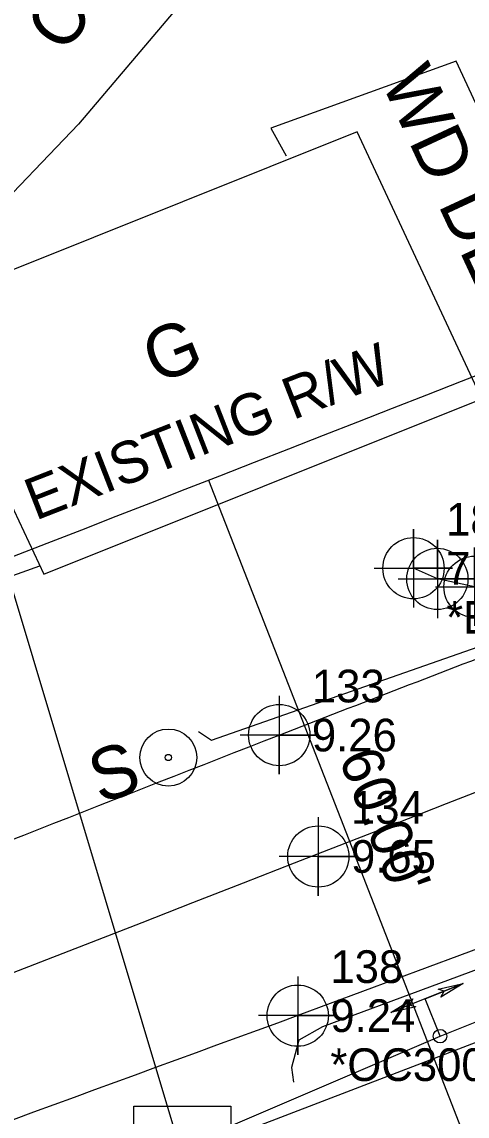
# Model space of a CAD drawing. Extents: x 2597630 to 2605918, y 617194 to 635093.
# Drawn here: x 2604013.5 to 2604047.6, y 618660.8 to 618744.5 of the extents above; entities that cross this region are included whole.
import ezdxf

# ---------------------------------------------------------------- set-up
doc = ezdxf.new("R2010")
doc.units = 0
for name, color, linetype in [('COGO Default Chain', 7, 'Continuous'), ('COGO Default Curve', 7, 'Continuous'), ('Default', 7, 'Continuous'), ('Exist Building', 7, 'Continuous'), ('Exist Building Text', 7, 'Continuous'), ('Exist DTM Crownline Cogo Elevation', 7, 'Continuous'), ('Exist DTM Crownline Cogo Number', 7, 'Continuous'), ('Exist DTM Crownline Cogo Point CELL', 7, 'Continuous'), ('Exist Guardrail', 7, 'Continuous'), ('Exist Horizontal Alignment', 7, 'Continuous'), ('Exist Horizontal Baseline Alignment Station Label', 7, 'Continuous'), ('Exist Other Culture Area Outline', 7, 'Continuous'), ('Exist Other Culture Area Outline Text', 7, 'Continuous'), ('Exist Other Culture Located Object CELL', 7, 'Continuous'), ('Exist Other Culture Located Object Text', 7, 'Continuous'), ('Exist Right of Way Line', 7, 'Continuous'), ('Exist Right of Way Line Text', 7, 'Continuous'), ('Exist Right of Way Width CELL', 7, 'Continuous'), ('Exist Roads EOP', 7, 'Continuous'), ('Exist Roads EOP Cogo Comment', 7, 'Continuous'), ('Exist Roads EOP Cogo Elevation', 7, 'Continuous'), ('Exist Roads EOP Cogo Number', 7, 'Continuous'), ('Exist Roads EOP Cogo Point CELL', 7, 'Continuous'), ('Exist Roads EOP Other', 7, 'Continuous'), ('Exist Roads EOP Other Text', 7, 'Continuous'), ('Exist Roads Soil', 7, 'Continuous'), ('Exist Structure Major Bridge WW', 7, 'Continuous'), ('Exist Structure Major Bridge WW Cogo Comment', 7, 'Continuous'), ('Exist Structure Major Bridge WW Cogo Elevation', 7, 'Continuous'), ('Exist Structure Major Bridge WW Cogo Number', 7, 'Continuous'), ('Exist Structure Major Bridge WW Cogo Point CELL', 7, 'Continuous'), ('Exist Utilities Water Change of Service SUE CELL', 7, 'Continuous'), ('Exist Utilities Water UG Line SUE LOS B', 7, 'Continuous'), ('Exist Utilities Water UG Line SUE LOS C', 7, 'Continuous')]:
    doc.layers.add(name, color=color, linetype=linetype)

# ---------------------------------------------------------------- blocks, each defined once
blk = doc.blocks.new('EXIST OTHER CULTURE LOCATED OBJECT')
at = {"layer": 'Exist Other Culture Located Object CELL'}
for radius in [0.0436, 0.0048]:
    blk.add_circle((0, 0), radius, dxfattribs=at)
blk = doc.blocks.new('CTL SUPPLEMENTAL HORIZONTAL AND VERTICAL')
at = {"layer": 'Default'}
blk.add_line((0, 0), (0, 0), dxfattribs=at)
blk.add_lwpolyline([(-0.1043, 0.0004), (0.0005, 0.1052), (0.1055, 0.0002), (0.0007, -0.1047)], close=True, dxfattribs=at)
blk = doc.blocks.new('EXIST DTM CROWNLINE COGO POINT')
at = {"layer": 'Exist DTM Crownline Cogo Point CELL'}
blk.add_lwpolyline([(0, 0.06), (0, -0.06), (0, 0), (0.06, 0), (-0.06, 0)], dxfattribs=at)
blk.add_circle((0, 0), 0.0469, dxfattribs=at)
blk = doc.blocks.new('EXIST ROADS EOP COGO POINT')
at = {"layer": 'Exist Roads EOP Cogo Point CELL'}
blk.add_lwpolyline([(0, 0.06), (0, -0.06), (0, 0), (0.06, 0), (-0.06, 0)], dxfattribs=at)
blk.add_circle((0, 0), 0.0469, dxfattribs=at)
blk = doc.blocks.new('EXIST STRUCTURE MAJOR BRIDGE WW COGO POINT')
at = {"layer": 'Exist Structure Major Bridge WW Cogo Point CELL'}
blk.add_lwpolyline([(-0.06, 0), (0.06, 0), (0, 0), (0, 0.06), (0, -0.06)], dxfattribs=at)
blk.add_circle((0, 0), 0.0469, dxfattribs=at)

msp = doc.modelspace()

# ---------------------------------------------------------------- linework, layer by layer
at = {"layer": 'COGO Default Chain'}
msp.add_line((2604025.781, 618657.828), (2604635.42, 618891.582), dxfattribs=at)
msp.add_line((2604025.781, 618657.828), (2604635.42, 618891.582), dxfattribs=at)
msp.add_arc((2597632.588, 635089.507), 17613.895, 290.3221155, 292.0583016, dxfattribs=at)
msp.add_arc((2597632.588, 635089.507), 17613.895, 290.3221155, 292.0583016, dxfattribs=at)
msp.add_arc((2597632.588, 635089.507), 17613.895, 290.3221155, 292.0583016, dxfattribs=at)
msp.add_arc((2597632.588, 635089.507), 17613.895, 290.3221155, 292.0583016, dxfattribs=at)
msp.add_arc((2597632.588, 635089.507), 17613.895, 290.3221155, 292.0583016, dxfattribs=at)
msp.add_arc((2597632.588, 635089.507), 17613.895, 290.3221155, 292.0583016, dxfattribs=at)
at = {"layer": 'COGO Default Curve'}
msp.add_arc((2597632.588, 635089.507), 17613.895, 290.3221155, 292.0583016, dxfattribs=at)
msp.add_arc((2597632.588, 635089.507), 17613.895, 290.3221155, 292.0583016, dxfattribs=at)
at = {"layer": 'Exist Building'}
msp.add_lwpolyline([(2604015.177, 618702.256), (2604048.721, 618715.695), (2604039.195, 618736.113), (2604005.593, 618722.673)], close=True, dxfattribs=at)
at = {"layer": 'Exist Guardrail'}
for points in [[(2604027.029, 618690.238), (2604028.032, 618689.57), (2604052.016, 618697.945)], [(2604059.732, 618676.217), (2604036.52, 618667.624), (2604034.721, 618666.608), (2604034.156, 618664.52), (2604034.305, 618663.39)]]:
    msp.add_lwpolyline(points, dxfattribs=at)
at = {"layer": 'Exist Horizontal Alignment'}
msp.add_arc((2597632.588, 635089.507), 17613.895, 290.3221155, 292.0583016, dxfattribs=at)
at = {"layer": 'Exist Horizontal Baseline Alignment Station Label'}
msp.add_line((2604025.781, 618657.828), (2603989.259, 618779.421), dxfattribs=at)
at = {"layer": 'Exist Other Culture Area Outline'}
msp.add_lwpolyline([(2604049.02, 618716.922), (2604056.77, 618719.992), (2604046.769, 618741.515), (2604032.571, 618736.399), (2604033.758, 618734.289)], dxfattribs=at)
at = {"layer": 'Exist Right of Way Line'}
for radius, start, end in [(17584.22, 290.3221155, 291.5057379), (17644.22, 291.0267478, 291.4331797)]:
    msp.add_arc((2597632.588, 635089.507), radius, start, end, dxfattribs=at)
at = {"layer": 'Exist Right of Way Width CELL'}
for p in [(2604027.809, 618709.46), (2604049.63, 618653.569)]:
    msp.add_line(p, (2604038.953, 618680.916), dxfattribs=at)
at = {"layer": 'Exist Roads EOP'}
msp.add_line((2604060.323, 618678.03), (2604034.633, 618668.486), dxfattribs=at)
for points in [[(2603230.17, 618389.98), (2603282.929, 618409.597), (2603332.773, 618427.868), (2603388.167, 618448.413), (2603437.203, 618466.721), (2603490.778, 618486.527), (2603539.039, 618504.558), (2603597.451, 618526.156), (2603651.053, 618545.972), (2603705.208, 618566.084), (2603762.02, 618587.183), (2603820.334, 618609.162), (2603876.341, 618629.99), (2603934.909, 618652.28), (2603996.409, 618675.568), (2604033.216, 618689.957), (2604052.01, 618697.199)], [(2604034.633, 618668.486), (2603984.89, 618650.123), (2603936.767, 618631.654), (2603888.195, 618613.335), (2603837.766, 618594.258), (2603782.918, 618573.705), (2603731.939, 618554.39), (2603671.126, 618532.171), (2603621.822, 618514.106), (2603561.545, 618491.877), (2603506.421, 618471.293), (2603452.163, 618451.33), (2603398.364, 618431.316), (2603341.431, 618410.355), (2603281.65, 618388.199), (2603223.033, 618366.475), (2603185.717, 618352.612)]]:
    msp.add_spline(points, degree=3, dxfattribs=at)
at = {"layer": 'Exist Roads EOP Other'}
msp.add_lwpolyline([(2604039.162, 618760.904), (2604028.995, 618750.493), (2604025.241, 618745.421), (2604017.836, 618736.698), (2604010.541, 618729.111), (2604004.643, 618721.649)], dxfattribs=at)
at = {"layer": 'Exist Roads Soil'}
msp.add_lwpolyline([(2604000.332, 618697.708), (2604014.876, 618702.897)], dxfattribs=at)
at = {"layer": 'Exist Structure Major Bridge WW'}
msp.add_lwpolyline([(2604050.92, 618700.387), (2604048.172, 618701.305), (2604045.325, 618701.901), (2604043.496, 618702.72)], dxfattribs=at)
at = {"layer": 'Exist Utilities Water Change of Service SUE CELL'}
for p, q in [((2604047.292, 618670.947), (2604041.759, 618668.724)), ((2604044.383, 618669.778), (2604047.292, 618670.947)), ((2604045.533, 618666.916), (2604044.383, 618669.778)), ((2604045.533, 618666.916), (2604045.533, 618666.916))]:
    msp.add_line(p, q, dxfattribs=at)
for points in [[(2604047.292, 618670.947), (2604045.591, 618669.893), (2604045.853, 618670.369), (2604045.385, 618670.51)], [(2604041.759, 618668.724), (2604043.46, 618669.778), (2604043.198, 618669.302), (2604043.667, 618669.161)]]:
    msp.add_lwpolyline(points, close=True, dxfattribs=at)
msp.add_circle((2604045.533, 618666.916), 0.517, dxfattribs=at)
at = {"layer": 'Exist Utilities Water UG Line SUE LOS B'}
msp.add_lwpolyline([(2603994.43, 618645.048), (2604045.533, 618666.916)], dxfattribs=at)
at = {"layer": 'Exist Utilities Water UG Line SUE LOS C'}
msp.add_line((2604045.533, 618666.916), (2604610.82, 618894.017), dxfattribs=at)

# ---------------------------------------------------------------- block references
at = {"layer": 'Default', "xscale": 50, "yscale": 49.99999999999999, "rotation": 44.99999999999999}
msp.add_blockref('CTL SUPPLEMENTAL HORIZONTAL AND VERTICAL', (2604025.781, 618657.828), dxfattribs=at)
at = {"layer": 'Exist DTM Crownline Cogo Point CELL', "xscale": 50, "yscale": 50}
msp.add_blockref('EXIST DTM CROWNLINE COGO POINT', (2604036.209, 618680.665), dxfattribs=at)
msp.add_blockref('EXIST DTM CROWNLINE COGO POINT', (2604036.209, 618680.665), dxfattribs=at)
at = {"layer": 'Exist Other Culture Located Object CELL', "xscale": 50, "yscale": 50}
msp.add_blockref('EXIST OTHER CULTURE LOCATED OBJECT', (2604024.726, 618688.238), dxfattribs=at)
at = {"layer": 'Exist Roads EOP Cogo Point CELL', "xscale": 50, "yscale": 50}
for p in [(2604033.216, 618689.957), (2604033.216, 618689.957), (2604034.633, 618668.486), (2604034.633, 618668.486)]:
    msp.add_blockref('EXIST ROADS EOP COGO POINT', p, dxfattribs=at)
at = {"layer": 'Exist Structure Major Bridge WW Cogo Point CELL', "xscale": 50, "yscale": 50}
for p in [(2604043.496, 618702.72), (2604043.496, 618702.72), (2604043.496, 618702.72), (2604045.325, 618701.901), (2604045.325, 618701.901), (2604045.325, 618701.901), (2604048.172, 618701.305), (2604048.172, 618701.305), (2604048.172, 618701.305)]:
    msp.add_blockref('EXIST STRUCTURE MAJOR BRIDGE WW COGO POINT', p, dxfattribs=at)

# ---------------------------------------------------------------- texts
at = {"layer": 'Exist Building Text'}
msp.add_text('G', height=4, rotation=21.7998, dxfattribs=at).set_placement((2604023.804, 618716.768))
at = {"layer": 'Exist DTM Crownline Cogo Elevation'}
msp.add_text('9.65', height=2.5, dxfattribs=at).set_placement((2604038.709, 618679.415))
at = {"layer": 'Exist DTM Crownline Cogo Number'}
msp.add_text('134', height=2.5, dxfattribs=at).set_placement((2604038.709, 618683.165))
msp.add_text('134', height=2.5, dxfattribs=at).set_placement((2604038.709, 618683.165))
at = {"layer": 'Exist Other Culture Area Outline Text'}
msp.add_text('WD DECK', height=4, rotation=294.92438, dxfattribs=at).set_placement((2604040.969, 618739.991))
at = {"layer": 'Exist Other Culture Located Object Text'}
msp.add_text('S', height=4, rotation=18.46282, dxfattribs=at).set_placement((2604019.483, 618684.675))
at = {"layer": 'Exist Right of Way Line Text'}
msp.add_text('EXISTING R/W', height=3.2, rotation=21.33491, dxfattribs=at).set_placement((2604014.548, 618706.347))
at = {"layer": 'Exist Right of Way Width CELL'}
msp.add_text("60.00'", height=3.2, rotation=291.32704, dxfattribs=at).set_placement((2604037.744, 618688.207))
at = {"layer": 'Exist Roads EOP Cogo Comment'}
msp.add_text('*OC3001', height=2.5, dxfattribs=at).set_placement((2604037.133, 618663.486))
at = {"layer": 'Exist Roads EOP Cogo Elevation'}
for s, p in [('9.26', (2604035.716, 618688.707)), ('9.24', (2604037.133, 618667.236))]:
    msp.add_text(s, height=2.5, dxfattribs=at).set_placement(p)
at = {"layer": 'Exist Roads EOP Cogo Number'}
for s, p in [('133', (2604035.716, 618692.457)), ('138', (2604037.133, 618670.986))]:
    msp.add_text(s, height=2.5, dxfattribs=at).set_placement(p)
at = {"layer": 'Exist Roads EOP Other Text'}
msp.add_text('CONC RAMP', height=4, rotation=52.23657, dxfattribs=at).set_placement((2604016.683, 618741.975))
at = {"layer": 'Exist Structure Major Bridge WW Cogo Comment'}
msp.add_text('*EL3119', height=2.5, dxfattribs=at).set_placement((2604045.996, 618697.72))
at = {"layer": 'Exist Structure Major Bridge WW Cogo Elevation'}
msp.add_text('7.06', height=2.5, dxfattribs=at).set_placement((2604045.996, 618701.47))
at = {"layer": 'Exist Structure Major Bridge WW Cogo Number'}
msp.add_text('181', height=2.5, dxfattribs=at).set_placement((2604045.996, 618705.22))

doc.saveas('drawing.dxf')
